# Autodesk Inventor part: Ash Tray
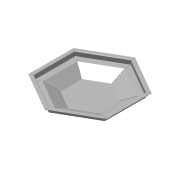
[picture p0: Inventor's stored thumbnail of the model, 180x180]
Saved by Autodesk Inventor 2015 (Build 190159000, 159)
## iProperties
Created: 2013-06
Part Number: Ash Tray
Material: Steel, Mild
Document SubType Name: Sheet Metal
Designer: 1103005
Density: 1 g/cm^3
Flat Pattern Width: 54.7697 cm
Flat Pattern Length: 61.1891 cm
Flat Pattern Area: 3351.31 cm^2
Sheet Metal Rule: Default_mm
Sheet Metal Width: 547.697 mm
Sheet Metal Length: 611.891 mm
Sheet Metal Area: 335130.875 mm^2
Appearance: Steel
Author: 1103005
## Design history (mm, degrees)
node "Face1"
node "Contour Flange2"
  sketch "Sketch2"
    geometry: L1 (0, 0)-(-115, 0) reference; L2 (-115, 0)-(-184.282, 40); L3 (-115, 0)-(-35, 0); L4 (-184.282, 40)-(-219.282, 40); L5 (-219.282, 40)-(-219.282, 67); L6 (-219.282, 67)-(-239.282, 67)
    constraints: 10 end point, 2 horizontal, 2 perpendicular, 1 equal length
    dimensions: "d62" = 80 distance of L1.end L2.end; "d63" = 150 deg angle of L3 L2; "d64" = 35 distance of L2.end L4.end; "d65" = 27 distance of L4.end L5.end; "d66" = 20 distance of L5.end L6.end
body "Solid1"
sketch "Sketch1"
  geometry: L1 (-115, 66.395)-(0, 132.791); L2 (0, 132.791)-(115, 66.395); L3 (115, 66.395)-(115, -66.395); L4 (115, -66.395)-(0, -132.791); L5 (0, -132.791)-(-115, -66.395); L6 (-115, -66.395)-(-115, 66.395); 3 further points
  constraints: 12 end point, 1 coincident, 1 vertical, 13 other
  dimensions: "d0" = 230 distance between parallel lines of L3 L6
face "Plate1" dims "Thickness" = 2
face "Plate3" dims "d67" = 2 (= BendReliefWidth), "d68" = 1 (= BendReliefDepth), "d69" = 4 (= MinimumRemnant), "d70" = 2 (= BendRadius), "d71" = 2 (= BendRadius), "d72" = 2, "d73" = 8 (= CornerReliefSize), "d74" = 1, "d75" = 2 (= JacobiRadiusSize), "SeamGap" = 0.01, "Thickness" = 2
bend "Bend2" dims "d67" = 2 (= BendReliefWidth), "d68" = 1 (= BendReliefDepth), "d69" = 4 (= MinimumRemnant), "d70" = 2 (= BendRadius), "d71" = 2 (= BendRadius), "d72" = 2, "SeamGap" = 0.01, "Thickness" = 2
feature "Corner2" dims "d72" = 2, "d73" = 8 (= CornerReliefSize), "d74" = 1, "d75" = 2 (= JacobiRadiusSize)
feature "Definition1"
other parameters: "BendRadius" = 2 (= Thickness), "BendReliefWidth" = 2 (= Thickness), "BendReliefDepth" = 1 (= 0.5 x Thickness), "CornerReliefSize" = 8 (= 4 x Thickness), "MinimumRemnant" = 4 (= 2 x Thickness), "TransitionRadius" = 2 (= BendRadius), "JacobiRadiusSize" = 2 (= BendRadius), "GapSize" = 2 (= Thickness), "d1" = 2 (= BendRadius), "BendRadius" = 2, "BendReliefDepth" = 1, "BendReliefWidth" = 2, "CornerReliefSize" = 8, "GapSize" = 2, "JacobiRadiusSize" = 2, "MinimumRemnant" = 4, "Thickness" = 2, "TransitionRadius" = 2
